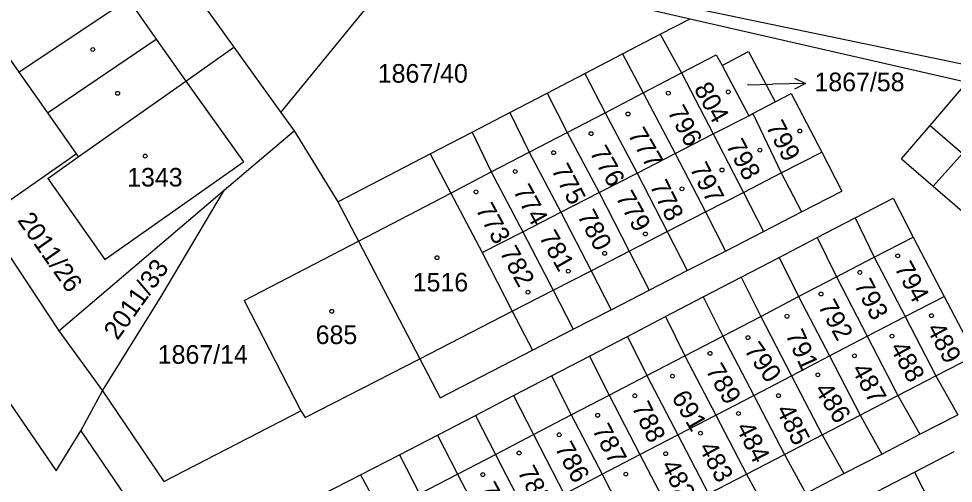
# Model space of a CAD drawing. Extents: x -763205 to -760228, y -1155311 to -1152844.
# Drawn here: x -761873.6 to -761788.3, y -1154630.9 to -1154588.5 of the extents above; entities that cross this region are included whole.
import ezdxf

# ---------------------------------------------------------------- set-up
doc = ezdxf.new("R2010")
doc.units = 0
for name, color, linetype in [('Vrstva 1', 7, 'Continuous'), ('Vrstva 16', 7, 'Continuous'), ('Vrstva 18', 7, 'Continuous'), ('Vrstva 19', 7, 'Continuous'), ('Vrstva 25', 7, 'Continuous'), ('Vrstva 4', 7, 'Continuous'), ('Vrstva 6', 7, 'Continuous')]:
    doc.layers.add(name, color=color, linetype=linetype)

msp = doc.modelspace()

# ---------------------------------------------------------------- linework, layer by layer
at = {"layer": 'Vrstva 1'}
for p, q in [((-761872.51, -1154565.13), (-761853.92, -1154591.08)), ((-761906.89, -1154576.2), (-761870.16, -1154629.76)), ((-761835.18, -1154583.23), (-761812.28, -1154588.49)), ((-761863.58, -1154586.67), (-761861.02, -1154590.34)), ((-761849.63, -1154597.05), (-761841.15, -1154586.63)), ((-761815.03, -1154589.91), (-761812.28, -1154588.49)), ((-761812.28, -1154588.49), (-761786.99, -1154594.29)), ((-761876.13, -1154589.71), (-761873.56, -1154593.38)), ((-761818.46, -1154591.7), (-761815.03, -1154589.91)), ((-761815.03, -1154589.91), (-761813.08, -1154593.44)), ((-761861.02, -1154590.34), (-761858.33, -1154594.19)), ((-761858.33, -1154594.19), (-761853.92, -1154591.08)), ((-761853.92, -1154591.08), (-761849.63, -1154597.05)), ((-761821.89, -1154593.49), (-761818.46, -1154591.7)), ((-761818.46, -1154591.7), (-761816.59, -1154595.26)), ((-761813.08, -1154593.44), (-761809.9, -1154591.78)), ((-761809.9, -1154591.78), (-761809.38, -1154592.75)), ((-761809.38, -1154592.75), (-761806.97, -1154591.47)), ((-761806.97, -1154591.47), (-761804.52, -1154596.09)), ((-761873.56, -1154593.38), (-761870.95, -1154597.09)), ((-761825.33, -1154595.27), (-761821.89, -1154593.49)), ((-761821.89, -1154593.49), (-761820.05, -1154597.07)), ((-761813.08, -1154593.44), (-761810.18, -1154599)), ((-761809.38, -1154592.75), (-761806.94, -1154597.35)), ((-761868.13, -1154601.1), (-761858.33, -1154594.19)), ((-761858.33, -1154594.19), (-761853.04, -1154601.55)), ((-761790.39, -1154598.25), (-761786.99, -1154594.29)), ((-761828.76, -1154597.06), (-761825.33, -1154595.27)), ((-761825.33, -1154595.27), (-761823.51, -1154598.87)), ((-761816.59, -1154595.26), (-761813.65, -1154600.79)), ((-761804.52, -1154596.09), (-761803.06, -1154595.33)), ((-761803.06, -1154595.33), (-761800.26, -1154600.66)), ((-761806.57, -1154597.15), (-761804.52, -1154596.09)), ((-761870.95, -1154597.09), (-761868.33, -1154600.81)), ((-761849.63, -1154597.05), (-761848.44, -1154598.71)), ((-761832.19, -1154598.84), (-761828.76, -1154597.06)), ((-761828.76, -1154597.06), (-761826.98, -1154600.67)), ((-761820.05, -1154597.07), (-761817.13, -1154602.58)), ((-761810.18, -1154599), (-761806.94, -1154597.35)), ((-761806.94, -1154597.35), (-761806.57, -1154597.15)), ((-761806.57, -1154597.15), (-761803.97, -1154602.57)), ((-761793.01, -1154601.29), (-761790.39, -1154598.25)), ((-761854.8, -1154604.12), (-761848.44, -1154598.71)), ((-761848.44, -1154598.71), (-761844.43, -1154605.21)), ((-761836.01, -1154600.82), (-761832.19, -1154598.84)), ((-761832.19, -1154598.84), (-761830.44, -1154602.48)), ((-761823.51, -1154598.87), (-761820.6, -1154604.36)), ((-761813.65, -1154600.79), (-761810.18, -1154599)), ((-761810.18, -1154599), (-761807.43, -1154604.35)), ((-761876.71, -1154606.69), (-761868.33, -1154600.81)), ((-761870.9, -1154603.07), (-761868.13, -1154601.1)), ((-761868.33, -1154600.81), (-761868.13, -1154601.1)), ((-761844.43, -1154605.21), (-761836.01, -1154600.82)), ((-761836.01, -1154600.82), (-761834.14, -1154604.41)), ((-761826.98, -1154600.67), (-761824.08, -1154606.15)), ((-761817.13, -1154602.58), (-761813.65, -1154600.79)), ((-761813.65, -1154600.79), (-761810.9, -1154606.13)), ((-761800.26, -1154600.66), (-761798.43, -1154604.22)), ((-761790.11, -1154603.78), (-761787.44, -1154600.78)), ((-761865.7, -1154610.48), (-761853.04, -1154601.55)), ((-761793.01, -1154601.29), (-761790.11, -1154603.78)), ((-761830.44, -1154602.48), (-761827.55, -1154607.94)), ((-761820.6, -1154604.36), (-761817.13, -1154602.58)), ((-761817.13, -1154602.58), (-761814.38, -1154607.92)), ((-761803.97, -1154602.57), (-761802.13, -1154606.13)), ((-761870.9, -1154603.07), (-761865.7, -1154610.48)), ((-761869.91, -1154616.97), (-761854.8, -1154604.12)), ((-761860.56, -1154613.84), (-761854.8, -1154604.12)), ((-761834.14, -1154604.41), (-761831.26, -1154609.84)), ((-761824.08, -1154606.15), (-761820.6, -1154604.36)), ((-761820.6, -1154604.36), (-761817.85, -1154609.71)), ((-761807.43, -1154604.35), (-761805.6, -1154607.91)), ((-761802.13, -1154606.13), (-761798.43, -1154604.22)), ((-761790.11, -1154603.78), (-761787.03, -1154606.43)), ((-761844.43, -1154605.21), (-761842.56, -1154608.79)), ((-761797.23, -1154606.67), (-761793.77, -1154604.87)), ((-761793.77, -1154604.87), (-761791.93, -1154608.42)), ((-761827.55, -1154607.94), (-761824.08, -1154606.15)), ((-761824.08, -1154606.15), (-761821.33, -1154611.49)), ((-761810.9, -1154606.13), (-761809.07, -1154609.7)), ((-761805.6, -1154607.91), (-761802.13, -1154606.13)), ((-761876.71, -1154606.69), (-761869.91, -1154616.97)), ((-761800.7, -1154608.47), (-761797.23, -1154606.67)), ((-761797.23, -1154606.67), (-761795.48, -1154610.27)), ((-761831.26, -1154609.84), (-761827.55, -1154607.94)), ((-761827.55, -1154607.94), (-761824.8, -1154613.28)), ((-761814.38, -1154607.92), (-761812.55, -1154611.48)), ((-761809.07, -1154609.7), (-761805.6, -1154607.91)), ((-761852.99, -1154614.22), (-761842.56, -1154608.79)), ((-761842.56, -1154608.79), (-761836.96, -1154619.53)), ((-761804.16, -1154610.28), (-761800.7, -1154608.47)), ((-761800.7, -1154608.47), (-761798.94, -1154612.06)), ((-761791.93, -1154608.42), (-761789.11, -1154613.84)), ((-761817.85, -1154609.71), (-761816.02, -1154613.27)), ((-761812.55, -1154611.48), (-761809.07, -1154609.7)), ((-761831.26, -1154609.84), (-761828.52, -1154615.19)), ((-761807.63, -1154612.08), (-761804.16, -1154610.28)), ((-761804.16, -1154610.28), (-761802.39, -1154613.86)), ((-761795.48, -1154610.27), (-761792.66, -1154615.68)), ((-761821.33, -1154611.49), (-761819.49, -1154615.06)), ((-761816.02, -1154613.27), (-761812.55, -1154611.48)), ((-761811.09, -1154613.88), (-761807.63, -1154612.08)), ((-761807.63, -1154612.08), (-761805.85, -1154615.66)), ((-761798.94, -1154612.06), (-761796.12, -1154617.48)), ((-761865.92, -1154622.45), (-761860.56, -1154613.84)), ((-761824.8, -1154613.28), (-761822.97, -1154616.84)), ((-761819.49, -1154615.06), (-761816.02, -1154613.27)), ((-761814.55, -1154615.68), (-761811.09, -1154613.88)), ((-761811.09, -1154613.88), (-761809.31, -1154617.46)), ((-761802.39, -1154613.86), (-761799.58, -1154619.28)), ((-761792.66, -1154615.68), (-761789.11, -1154613.84)), ((-761789.11, -1154613.84), (-761786.29, -1154619.24)), ((-761852.99, -1154614.22), (-761847.81, -1154624.3)), ((-761828.52, -1154615.19), (-761826.68, -1154618.75)), ((-761822.97, -1154616.84), (-761819.49, -1154615.06)), ((-761818.02, -1154617.49), (-761814.55, -1154615.68)), ((-761814.55, -1154615.68), (-761812.77, -1154619.26)), ((-761805.85, -1154615.66), (-761803.03, -1154621.08)), ((-761796.12, -1154617.48), (-761792.66, -1154615.68)), ((-761792.66, -1154615.68), (-761789.88, -1154621.1)), ((-761869.91, -1154616.97), (-761865.92, -1154622.45)), ((-761826.68, -1154618.75), (-761822.97, -1154616.84)), ((-761821.48, -1154619.29), (-761818.02, -1154617.49)), ((-761818.02, -1154617.49), (-761816.23, -1154621.06)), ((-761809.31, -1154617.46), (-761806.49, -1154622.88)), ((-761799.58, -1154619.28), (-761796.12, -1154617.48)), ((-761796.12, -1154617.48), (-761793.33, -1154622.9)), ((-761835.09, -1154623.11), (-761826.68, -1154618.75)), ((-761847.42, -1154624.91), (-761836.96, -1154619.53)), ((-761836.96, -1154619.53), (-761835.09, -1154623.11)), ((-761824.94, -1154621.09), (-761821.48, -1154619.29)), ((-761821.48, -1154619.29), (-761819.69, -1154622.86)), ((-761812.77, -1154619.26), (-761809.95, -1154624.68)), ((-761803.03, -1154621.08), (-761799.58, -1154619.28)), ((-761799.58, -1154619.28), (-761796.78, -1154624.69)), ((-761828.41, -1154622.89), (-761824.94, -1154621.09)), ((-761824.94, -1154621.09), (-761823.15, -1154624.66)), ((-761816.23, -1154621.06), (-761813.41, -1154626.48)), ((-761806.49, -1154622.88), (-761803.03, -1154621.08)), ((-761803.03, -1154621.08), (-761800.24, -1154626.48)), ((-761789.88, -1154621.1), (-761787.87, -1154624.64)), ((-761867.91, -1154626.12), (-761865.92, -1154622.45)), ((-761865.92, -1154622.45), (-761860.32, -1154630.75)), ((-761831.87, -1154624.7), (-761828.41, -1154622.89)), ((-761828.41, -1154622.89), (-761826.6, -1154626.46)), ((-761819.69, -1154622.86), (-761816.87, -1154628.28)), ((-761809.95, -1154624.68), (-761806.49, -1154622.88)), ((-761806.49, -1154622.88), (-761803.69, -1154628.28)), ((-761793.33, -1154622.9), (-761791.34, -1154626.43)), ((-761860.32, -1154630.75), (-761847.81, -1154624.3)), ((-761847.81, -1154624.3), (-761847.42, -1154624.91)), ((-761835.34, -1154626.5), (-761831.87, -1154624.7)), ((-761831.87, -1154624.7), (-761830.06, -1154628.26)), ((-761823.15, -1154624.66), (-761820.33, -1154630.08)), ((-761813.41, -1154626.48), (-761809.95, -1154624.68)), ((-761809.95, -1154624.68), (-761807.15, -1154630.07)), ((-761796.78, -1154624.69), (-761794.8, -1154628.23)), ((-761791.34, -1154626.43), (-761787.87, -1154624.64)), ((-761870.16, -1154629.76), (-761867.91, -1154626.12)), ((-761867.91, -1154626.12), (-761828.53, -1154683.64)), ((-761838.8, -1154628.3), (-761835.34, -1154626.5)), ((-761835.34, -1154626.5), (-761833.52, -1154630.06)), ((-761826.6, -1154626.46), (-761823.78, -1154631.88)), ((-761816.87, -1154628.28), (-761813.41, -1154626.48)), ((-761813.41, -1154626.48), (-761810.6, -1154631.86)), ((-761800.24, -1154626.48), (-761798.26, -1154630.02)), ((-761794.8, -1154628.23), (-761791.34, -1154626.43)), ((-761842.36, -1154630.13), (-761838.8, -1154628.3)), ((-761838.8, -1154628.3), (-761836.98, -1154631.86)), ((-761830.06, -1154628.26), (-761827.24, -1154633.68)), ((-761820.33, -1154630.08), (-761816.87, -1154628.28)), ((-761816.87, -1154628.28), (-761814.05, -1154633.66)), ((-761803.69, -1154628.28), (-761801.73, -1154631.82)), ((-761798.26, -1154630.02), (-761794.8, -1154628.23)), ((-761791.8, -1154629.88), (-761788.2, -1154628.01)), ((-761845.92, -1154631.95), (-761842.36, -1154630.13)), ((-761842.36, -1154630.13), (-761840.44, -1154633.66)), ((-761833.52, -1154630.06), (-761830.7, -1154635.48)), ((-761823.78, -1154631.88), (-761820.33, -1154630.08)), ((-761820.33, -1154630.08), (-761817.51, -1154635.45)), ((-761807.15, -1154630.07), (-761805.19, -1154633.61)), ((-761801.73, -1154631.82), (-761798.26, -1154630.02)), ((-761795.27, -1154631.67), (-761791.8, -1154629.88)), ((-761791.8, -1154629.88), (-761789.99, -1154633.48))]:
    msp.add_line(p, q, dxfattribs=at)
at = {"layer": 'Vrstva 16'}
for p in [(-761807.03, -1154594.51), (-761801.761, -1154594.389)]:
    msp.add_line(p, (-761804.76, -1154594.46), dxfattribs=at)
msp.add_lwpolyline([(-761802.772, -1154593.913), (-761801.761, -1154594.389), (-761802.749, -1154594.913)], dxfattribs=at)
at = {"layer": 'Vrstva 25'}
for centre in [(-761866.8, -1154591.3), (-761864.54, -1154595.3), (-761814.28, -1154595.28), (-761808.81, -1154595.17), (-761817.96, -1154597.18), (-761802.28, -1154598.74), (-761821.33, -1154598.98), (-761805.93, -1154600.49), (-761862.03, -1154601.03), (-761824.75, -1154600.72), (-761828.26, -1154602.44), (-761809.38, -1154602.3), (-761831.83, -1154604.3), (-761813.03, -1154604.02), (-761816.37, -1154608.14), (-761835.39, -1154610.31), (-761820.09, -1154609.91), (-761793.34, -1154610.14), (-761823.41, -1154611.53), (-761796.8, -1154611.65), (-761827.09, -1154613.45), (-761800.34, -1154613.62), (-761845, -1154615.2), (-761803.45, -1154615.65), (-761790.26, -1154615.6), (-761793.86, -1154617.47), (-761807.01, -1154617.6), (-761810.47, -1154619.04), (-761797.29, -1154619.27), (-761813.9, -1154621.12), (-761800.63, -1154621), (-761817.34, -1154622.91), (-761804.23, -1154622.9), (-761820.73, -1154624.69), (-761807.88, -1154624.53), (-761824.24, -1154626.47), (-761811.34, -1154626.32), (-761827.9, -1154628.14), (-761814.52, -1154628.2), (-761831.21, -1154630.11), (-761818.16, -1154630.07)]:
    msp.add_circle(centre, 0.175, dxfattribs=at)
at = {"layer": 'Vrstva 4'}
for p, q in [((-761873.56, -1154593.38), (-761863.58, -1154586.67)), ((-761870.95, -1154597.09), (-761861.02, -1154590.34)), ((-761816.59, -1154595.26), (-761813.08, -1154593.44)), ((-761820.05, -1154597.07), (-761816.59, -1154595.26)), ((-761823.51, -1154598.87), (-761820.05, -1154597.07)), ((-761790.39, -1154598.25), (-761787.44, -1154600.78)), ((-761826.98, -1154600.67), (-761823.51, -1154598.87)), ((-761830.44, -1154602.48), (-761826.98, -1154600.67)), ((-761803.97, -1154602.57), (-761800.26, -1154600.66)), ((-761834.14, -1154604.41), (-761830.44, -1154602.48)), ((-761807.43, -1154604.35), (-761803.97, -1154602.57)), ((-761842.56, -1154608.79), (-761834.14, -1154604.41)), ((-761810.9, -1154606.13), (-761807.43, -1154604.35)), ((-761814.38, -1154607.92), (-761810.9, -1154606.13)), ((-761817.85, -1154609.71), (-761814.38, -1154607.92)), ((-761795.48, -1154610.27), (-761791.93, -1154608.42)), ((-761821.33, -1154611.49), (-761817.85, -1154609.71)), ((-761798.94, -1154612.06), (-761795.48, -1154610.27)), ((-761824.8, -1154613.28), (-761821.33, -1154611.49)), ((-761802.39, -1154613.86), (-761798.94, -1154612.06)), ((-761828.52, -1154615.19), (-761824.8, -1154613.28)), ((-761805.85, -1154615.66), (-761802.39, -1154613.86)), ((-761836.96, -1154619.53), (-761828.52, -1154615.19)), ((-761809.31, -1154617.46), (-761805.85, -1154615.66)), ((-761812.77, -1154619.26), (-761809.31, -1154617.46)), ((-761816.23, -1154621.06), (-761812.77, -1154619.26)), ((-761789.88, -1154621.1), (-761786.29, -1154619.24)), ((-761819.69, -1154622.86), (-761816.23, -1154621.06)), ((-761793.33, -1154622.9), (-761789.88, -1154621.1)), ((-761823.15, -1154624.66), (-761819.69, -1154622.86)), ((-761796.78, -1154624.69), (-761793.33, -1154622.9)), ((-761826.6, -1154626.46), (-761823.15, -1154624.66)), ((-761800.24, -1154626.48), (-761796.78, -1154624.69)), ((-761830.06, -1154628.26), (-761826.6, -1154626.46)), ((-761803.69, -1154628.28), (-761800.24, -1154626.48)), ((-761833.52, -1154630.06), (-761830.06, -1154628.26)), ((-761807.15, -1154630.07), (-761803.69, -1154628.28)), ((-761836.98, -1154631.86), (-761833.52, -1154630.06)), ((-761810.6, -1154631.86), (-761807.15, -1154630.07))]:
    msp.add_line(p, q, dxfattribs=at)
at = {"layer": 'Vrstva 6'}
msp.add_line((-761814.98, -1154586.9), (-761784.4, -1154593.25), dxfattribs=at)

# ---------------------------------------------------------------- texts
at = {"layer": 'Vrstva 16'}
msp.add_text('1867/58', height=1.7, dxfattribs=at).set_placement((-761800.937, -1154595.11))
at = {"layer": 'Vrstva 18'}
for s, height, p in [('1867/40', 1.7, (-761840.797, -1154594.33)), ('1867/58', 0.1, (-761807.296, -1154594.51)), ('1867/14', 1.7, (-761860.877, -1154619.99))]:
    msp.add_text(s, height=height, dxfattribs=at).set_placement(p)
for s, rotation, p in [('2011/26', 304.98543, (-761873.744, -1154606.895)), ('2011/33', 54.60288, (-761864.553, -1154617.919))]:
    msp.add_text(s, height=1.7, rotation=rotation, dxfattribs=at).set_placement(p)
at = {"layer": 'Vrstva 19'}
for s, rotation, p in [('804', 299.31315, (-761811.994, -1154594.877)), ('796', 298.6256, (-761814.406, -1154596.978)), ('799', 297.47969, (-761805.41, -1154598.321)), ('777', 300.22988, (-761818.02, -1154599.055)), ('798', 298.05264, (-761809.058, -1154600.04)), ('776', 299.37045, (-761821.494, -1154600.677)), ('775', 297.93805, (-761824.999, -1154602.28)), ('797', 297.36509, (-761812.361, -1154602.151)), ('774', 299.14126, (-761828.504, -1154604.207)), ('778', 296.50566, (-761816.014, -1154603.732)), ('779', 299.14126, (-761819.124, -1154604.787)), ('773', 298.56831, (-761831.906, -1154605.889)), ('780', 297.76617, (-761822.629, -1154606.47)), ('781', 299.88611, (-761826.132, -1154608.416)), ('782', 298.74019, (-761829.716, -1154609.808)), ('794', 298.39642, (-761793.687, -1154611.229)), ('793', 297.13591, (-761797.362, -1154612.781)), ('792', 298.96938, (-761800.655, -1154614.718)), ('791', 294.50031, (-761803.622, -1154617.326)), ('489', 298.16724, (-761790.748, -1154616.779)), ('790', 304.98543, (-761807.414, -1154618.755)), ('488', 298.56831, (-761794.096, -1154618.519)), ('789', 300.22988, (-761810.92, -1154620.585)), ('487', 298.91208, (-761797.605, -1154620.508)), ('691', 300.11529, (-761814.041, -1154623.029)), ('486', 302.40713, (-761800.993, -1154622.37)), ('788', 295.99, (-761817.646, -1154623.943)), ('485', 296.73484, (-761804.493, -1154624.202)), ('787', 297.82346, (-761821.269, -1154626.02)), ('484', 296.62025, (-761808.154, -1154625.802)), ('786', 298.22453, (-761824.678, -1154627.669)), ('483', 298.10994, (-761811.548, -1154627.639)), ('785', 297.47969, (-761828.09, -1154629.841)), ('482', 297.53698, (-761814.99, -1154629.271)), ('784', 299.14126, (-761831.644, -1154631.387))]:
    msp.add_text(s, height=1.7, rotation=rotation, dxfattribs=at).set_placement(p)
for s, p in [('1343', (-761863.667, -1154603.81)), ('1516', (-761837.604, -1154613.39)), ('685', (-761846.463, -1154618.19))]:
    msp.add_text(s, height=1.7, dxfattribs=at).set_placement(p)

doc.saveas('drawing.dxf')
